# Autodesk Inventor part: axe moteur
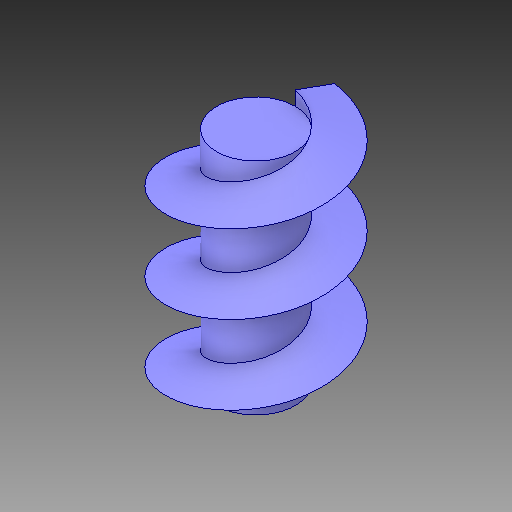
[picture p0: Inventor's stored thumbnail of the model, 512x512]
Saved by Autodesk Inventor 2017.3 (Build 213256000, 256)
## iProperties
Created: 2007-12
Part Number: axe moteur
Material: Générique
Document SubType Name: Modeling
Designer: ficho
Density: 1 g/cm^3
Appearance: Par défaut
Author: ficho
Sending System: SolidWorks 2009
Last Author: christophe
Last Saved: 2011-01-23
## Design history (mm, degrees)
extrude "Extrusion2"
node "Solide1"
